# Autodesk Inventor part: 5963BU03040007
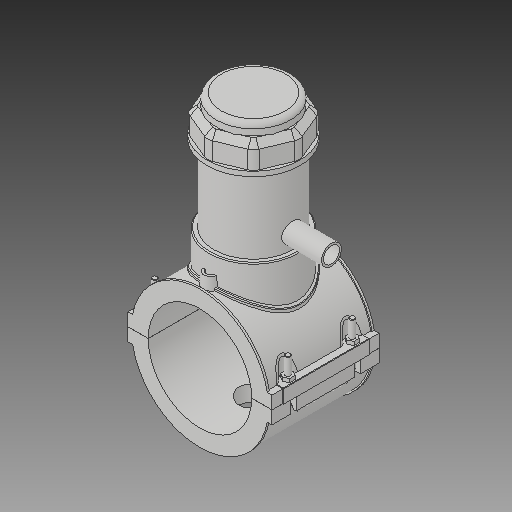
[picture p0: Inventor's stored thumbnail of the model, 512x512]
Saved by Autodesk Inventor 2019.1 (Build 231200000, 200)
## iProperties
Created: 2017-07
Part Number: 5963BU03040007
Material: Generic
Description: PLASSON TAPPING SADDLE 4''IPS x 1 3/4''CTS
Document SubType Name: Modeling
Designer: KIM
Mass: 1712.7 g
Surface Area: 2671.49 cm^2
Volume: 1712.7 cm^3
Density: 1 g/cm^3
Appearance: Default
Author: KIM
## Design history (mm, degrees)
derived "5963B.ipt"
feature "Solid1::5963B.ipt"
feature "Solid2::5963B.ipt"
feature "Solid4::5963B.ipt"
feature "Solid5::5963B.ipt"
tag "TaggingFeature1"
body "Solid1"
body "Solid2"
other parameters: "d0" = 114.1, "d2" = 159.004, "d3" = 28.525, "d4" = 118.11, "d5" = 0, "d6" = 0.1, "d8" = 0, "d19" = 6, "d20" = 6, "d21" = 70.866, "d23" = 0, "d24" = 35.433, "d26" = 0, "d29" = 3, "d30" = 38.03333, "d31" = 6, "d32" = 0, "d33" = 0, "d34" = 0.6, "d40" = 77.1316, "d41" = 102.69, "d43" = 0, "d45" = 0, "d47" = 145.031, "d70" = 15, "d72" = 0, "d73" = 6, "d75" = 5, "d76" = 0, "d77" = 5.705, "d78" = 87.05, "d79" = 15, "d80" = 47.244, "d82" = 5 deg, "d84" = 4, "d85" = 14, "d86" = 0, "d87" = 3, "d88" = 0, "d89" = 1, "d90" = 1, "d91" = 94.488, "d92" = 0, "d93" = 0.5, "d94" = 60.05263, "d96" = 151.2966, "d97" = 2.3622, "d98" = 0, "d102" = 1.141, "d120" = 140 deg, "d121" = 24.228, "d122" = 20 deg, "d123" = 296.66, "d124" = 88.998, "d126" = 0, "d143" = 117.523, "d145" = 26.33077, "d149" = 1.7115, "d150" = 28.96385, "d153" = 118.11, "d154" = 0, "d156" = 74.165, "d157" = 160 deg, "d159" = 6.846, "d161" = 1.7115, "d162" = 70.866, "d163" = 0, "d164" = 57.05, "d167" = 11.41, "d168" = 72.3561, "d170" = 3.2805, "d172" = 0, "d173" = 1, "d175" = 57.05, "d176" = 20 deg, "d177" = 7.987, "d178" = 34.23, "d180" = 0, "d183" = 13.692, "d184" = 6.3896, "d185" = 38.38575, "d186" = 38.38575, "d187" = 74.165, "d188" = 10.269, "d189" = 7.987, "d190" = 0, "d191" = 111.2475, "d193" = 6.1236, "d194" = 4.13385, "d195" = 90 deg, "d197" = 0, "d199" = 0, "d200" = 17.115, "d202" = 0, "d203" = 177.038, "d204" = 97.5555, "d205" = 71.883, "d206" = 87.2865, "d207" = 132.7785, "d208" = 138.08964, "d209" = 164.64534, "d210" = 88.3134, "d211" = 102.69, "d212" = 82.152, "d213" = 48.5766, "d216" = 0, "d217" = 11.41, "d218" = 5.705, "d219" = 1.141, "d222" = 114.1, "d224" = 0, "d230" = 6.846, "d233" = 6, "d236" = 79.502, "d237" = 35.433, "d238" = 6.02433, "d240" = 35.433, "d241" = 35.433, "d242" = 35.433, "d243" = 6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
